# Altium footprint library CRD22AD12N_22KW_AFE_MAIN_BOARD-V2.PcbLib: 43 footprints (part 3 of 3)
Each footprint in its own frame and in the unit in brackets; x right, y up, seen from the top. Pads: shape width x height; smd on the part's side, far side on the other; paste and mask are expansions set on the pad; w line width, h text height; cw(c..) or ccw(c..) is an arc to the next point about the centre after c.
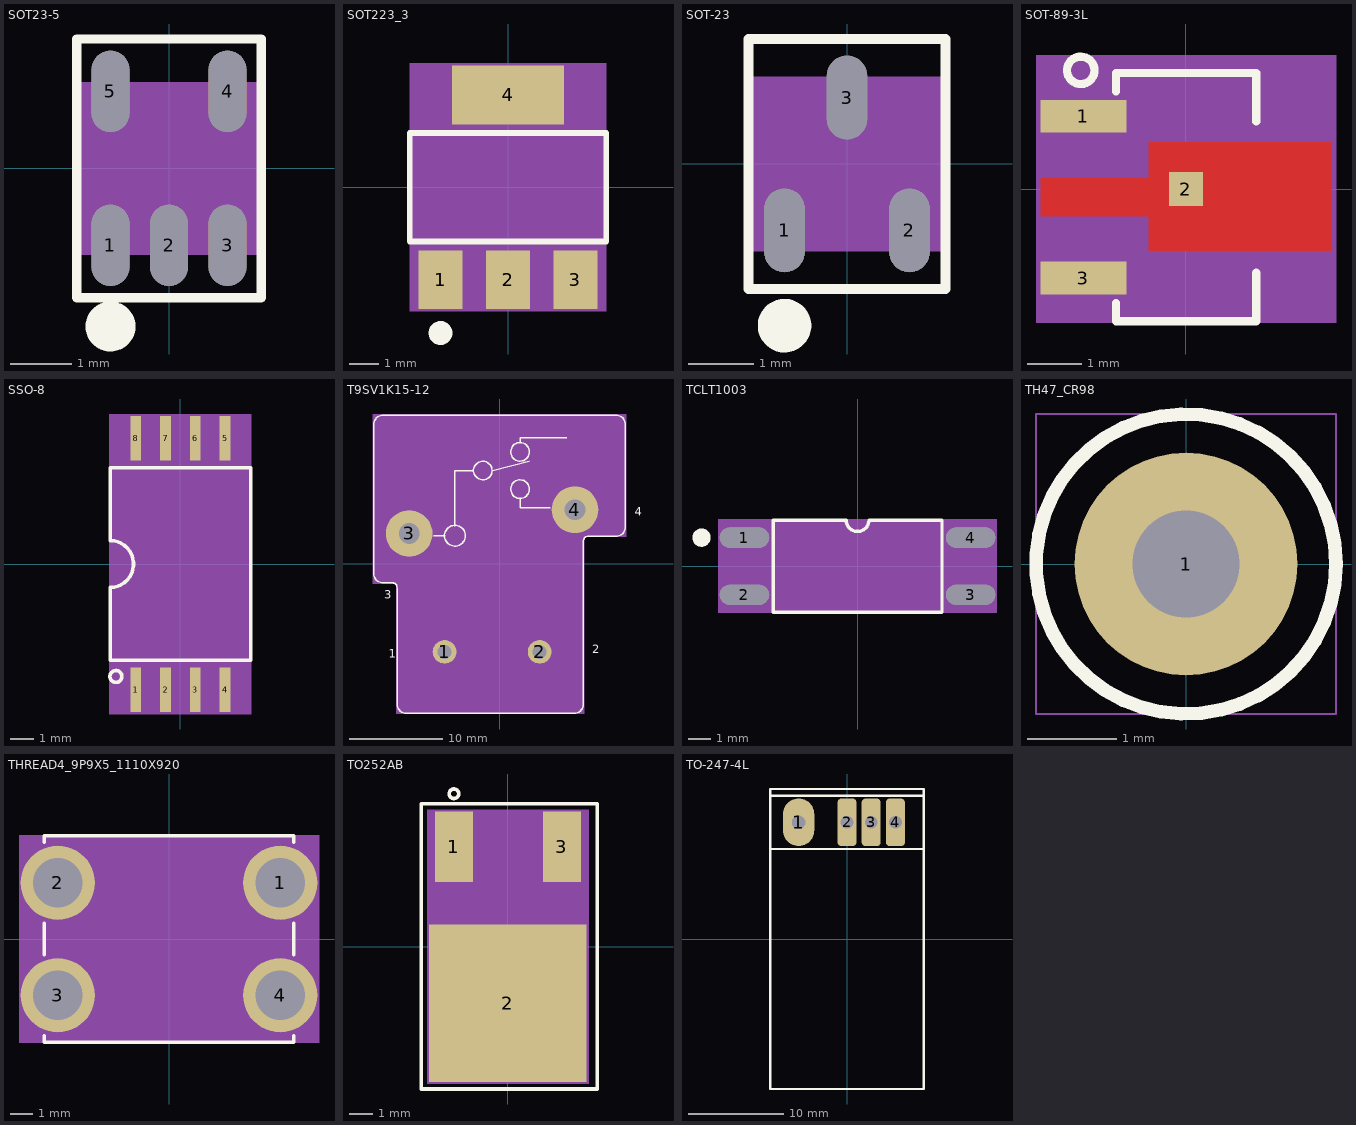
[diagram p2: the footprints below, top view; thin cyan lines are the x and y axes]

## SOT23-5 [mil] "SOT23-5"
pads (5):
  oval 24x52 smd: 1(-37.4,-49.21) 2(0,-49.21) 3(37.4,-49.21) 4(37.4,49.21) 5(-37.4,49.21)
Top Overlay:
  circle w16: c-37.4,-101.11 r8
  lines w6: -59.05,-82.68 59.05,-82.68 59.05,82.68 -59.05,82.68 -59.05,-82.68
Top Courtyard:
  dashed: -57.09,-55.12 -57.09,55.12 57.09,55.12 57.09,-55.12
Top 3D Body:
  region: -57.09,-55.12 -57.09,55.12 57.09,55.12 57.09,-55.12
Top Component Center:
  lines w3: -20,0 20,0 ; 0,-20 0,20
Top Assembly:
  lines w2: -59.05,-33.47 59.05,-33.47 59.05,33.47 -59.05,33.47 -59.05,-33.47
  text "HAMP" at 0,33.6 h31
  text "#TOL" at 0,33.6 h31
  text "MCP6031" at 0,70.8 h31
  text ".Designator" at 0,22 h35
Mechanical 24:
  text "2" at 1.97,-39.41 h25
  text "5" at -39.37,59.41 h25
  text "1" at -37.4,-37.44 h25
  text "3" at 37.4,-39.41 h25
  text "4" at 37.4,59.41 h25
3D body: height 150, standoff 0, extent -57.09,-55.12 57.09,55.12

## SOT223_3 [mil] "SOT223_3"
pads (4):
  rect 59x79 smd: 1(-90.55,-124.02) 2(0,-124.02) 3(90.55,-124.02)
  rect 150x79 smd: 4(0,124.02)
Top Overlay:
  circle w16: c-90.55,-195.52 r8
  lines w7.87: -131.89,-72.84 131.89,-72.84 131.89,72.84 -131.89,72.84 -131.89,-72.84
  text ".Designator" at 245,11.67 h35
Top Courtyard:
  dashed: -131.89,-166.52 131.89,-166.52 131.89,166.52 -131.89,166.52
Top 3D Body:
  region: -131.89,-166.52 131.89,-166.52 131.89,166.52 -131.89,166.52
Top Component Center:
  lines w3: -20,0 20,0 ; 0,-20 0,20
Top Assembly:
  lines w1: -131.89,-72.84 131.89,-72.84 131.89,72.84 -131.89,72.84 -131.89,-72.84
  text "HAMP" at 49.6,-16 h31
  text "#TOL" at 49.6,-16 h31
  text "LT3092EST_SOT223_5" at 223.2,-16 h31
Mechanical 24:
  text "3" at 109.75,-124.02 h48
  text "1" at -71.35,-124.02 h48
  text "4" at 19.2,124.02 h48
  text "2" at 19.2,-124.02 h48
Mechanical 26:
  dashed: -127.95,-166.52 127.95,-166.52 127.95,166.52 -127.95,166.52
3D body: height 150, standoff 0, extent -131.89,-166.52 131.89,166.52

## SOT-23 [mil] "SOT-23"
pads (3):
  oval 24x50 smd: 1(-37.4,-39.76) 2(37.4,-39.76) 3(0,39.76)
Top Overlay:
  circle w16: c-37.4,-96.77 r8.01
  lines w6: -59.06,-74.8 -59.06,74.8 59.06,74.8 59.06,-74.8 -59.06,-74.8
  text ".Designator" at -30,88.33 h35
Top Courtyard:
  lines w1: -59.84,-51.97 -59.84,51.97 59.84,51.97 59.84,-51.97 -59.84,-51.97
Top 3D Body:
  region: -59.84,-51.97 -59.84,51.97 59.84,51.97 59.84,-51.97
Top Component Center:
  lines w3: -20,0 20,0 ; 0,-20 0,20
Top Assembly:
  lines w2: -59.06,-27.56 59.06,-27.56 59.06,27.56 -59.06,27.56 -59.06,-27.56
  text "HAMP" at 0,-65.6 h31
  text "#TOL" at 0,-65.6 h31
  text "2N7002K" at 0,-102.8 h31
Mechanical 24:
  text "2" at 37.4,-43.76 h10
  text "3" at 0,35.76 h10
  text "1" at -37.4,-43.76 h10
3D body: height 150, standoff 0, extent -59.84,-51.97 59.84,51.97

## SOT-89-3L [mil] "SOT-89-3L"
pads (3):
  rect 63x24 smd: 1(-74.78,53.08) 3(-74.78,-65.03)
  rect 25x25 smd mask+0: 2(0,0)
Top Layer:
  region: -106,-20 -106,8 -27,8 -27,34 106,34 106,-45 -27,-45 -27,-20
Top Overlay:
  circle w6: c-76.75,86.54 r10
  lines w6: -51.15,-83.13 -51.15,-96.53 51.21,-96.53 51.21,-61.1 ; -51.15,71.18 -51.15,84.57 51.21,84.57 51.21,49.14
  text ".Designator" at 120,-11.67 h35
Top Courtyard:
  dashed: -109.4,-97.53 109.4,-97.53 109.4,97.53 -109.4,97.53
Top 3D Body:
  region: -109.4,-97.53 109.4,-97.53 109.4,97.53 -109.4,97.53
Top Component Center:
  lines w3: -37.69,-5.98 2.31,-5.98 ; -17.69,-25.98 -17.69,14.02
Top Assembly:
  circle w2: c-76.75,86.54 r10
  lines w2: -51.15,-80.78 -51.15,-96.53 51.21,-96.53 51.21,-61.1 ; -51.15,68.82 -51.15,84.57 51.21,84.57 51.21,49.14
  text "MC78L05F-TP" at -17.69,114.42 h31
  text "#TOL" at -17.69,27.62 h31
  text "HAMP" at -17.69,27.62 h31
Mechanical 24:
  text "1" at -74.78,57.08 h10
  text "3" at -74.78,-61.03 h10
  text "2" at -66.9,-1.98 h10
3D body: height 150, standoff 0, extent -109.4,-97.53 109.4,97.53

## SSO-8 [mil] "SSO-8"
pads (8):
  rect 18x75 smd: 1(-74.84,-211.52) 2(-24.84,-211.52) 3(25.16,-211.52) 4(75.16,-211.52) 5(75.16,211.52) 6(25.16,211.52) 7(-24.84,211.52) 8(-74.84,211.52)
Top Overlay:
  circle w6: c-108.27,-188.98 r10
  lines w6: -117.95,-161.42 -117.95,-39.37 ccw(c-117.95,0) -117.95,39.37 -117.95,161.42 118.27,161.42 118.27,-161.42 -117.95,-161.42
  text ".Designator" at 70,311.67 h35
Top Courtyard:
  dashed: -119.27,-252.02 119.27,-252.02 119.27,252.02 -119.27,252.02
Top 3D Body:
  region: -119.27,-252.02 119.27,-252.02 119.27,252.02 -119.27,252.02
Top Component Center:
  lines w3: -19.84,0 20.16,0 ; 0.16,-20 0.16,20
Top Assembly:
  circle w2: c-108.27,-188.98 r10
  lines w2: -117.95,-161.42 -117.95,-39.37 ccw(c-117.95,0) -117.95,39.37 -117.95,161.42 118.27,161.42 118.27,-161.42 -117.95,-161.42
  text "ACPL-C870-500E" at 173.76,-16 h31
  text "#TOL" at 49.76,-16 h31
  text "HAMP" at 49.76,-16 h31
Mechanical 24:
  text "6" at 29.16,211.52 h10
  text "3" at 29.16,-211.52 h10
  text "4" at 79.16,-211.52 h10
  text "5" at 79.16,211.52 h10
  text "8" at -70.84,211.52 h10
  text "7" at -20.84,211.52 h10
  text "2" at -20.84,-211.52 h10
  text "1" at -70.84,-211.52 h10
3D body: height 150, standoff 0, extent -119.27,-252.02 119.27,252.02

## T9SV1K15-12 [mil] "T9SV1K15-12"
pads (4):
  round 100 hole 59: 1(-232.28,-371.06) 2(169.3,-371.06)
  round 197 hole 87: 3(-381.88,128.94) 4(318.9,229.34)
Top Overlay:
  circle w5.91: c86.61,473.82 r39.37
  circle w5.91: c86.61,316.34 r39.37
  circle w5.91: c-70.86,395.08 r39.37
  circle w5.91: c-188.97,119.49 r44.02
  lines w5.91: -452.75,-79.73 cw(c-452.76,-99.4) -433.08,-99.41 -433.08,-591.54 ccw(c-393.71,-591.53) -393.71,-630.91 314.97,-630.91 ccw(c314.97,-591.53) 354.34,-591.54 354.34,97.44 cw(c374.02,97.45) 374.01,117.12 492.12,117.12 ccw(c492.12,156.5) 531.49,156.5 531.49,176.18 531.49,589.57 ccw(c492.12,589.57) 492.12,628.94 -492.12,628.94 ccw(c-492.12,589.57) -531.49,589.57 -531.49,-40.35 ccw(c-492.12,-40.35) -492.12,-79.72 -452.75,-79.72 ; -277.33,119.49 -228.34,119.49 ; -188.97,158.85 -188.97,395.07 -110.23,395.07 ; -31.49,395.07 125.99,434.44 ; 86.62,276.96 86.62,237.59 214.34,237.59 ; 86.62,513.18 86.62,532.88 283.47,532.88
  text ".Designator" at 432.01,-146.73 h35
  text "3" at -487.99,-146.73 h35
  text "4" at 572.01,203.27 h35
  text "2" at 392.01,-376.73 h35
  text "1" at -467.99,-396.73 h35
Top 3D Body:
  region: -535.43,633.85 535.43,633.85 535.43,114.18 358.27,114.18 358.27,-633.86 -437.01,-633.86 -437.01,-82.67 -535.43,-82.67
Top Component Center:
  lines w3: -51.49,-70.86 -11.49,-70.86 ; -31.49,-90.86 -31.49,-50.86
Top Assembly:
  circle w2: c86.61,473.82 r39.37
  circle w2: c86.61,316.34 r39.37
  circle w2: c-70.86,395.08 r39.37
  circle w2: c-188.97,119.49 r44.02
  lines w2: -452.75,-79.73 cw(c-452.76,-99.4) -433.08,-99.41 -433.08,-591.54 ccw(c-393.71,-591.53) -393.71,-630.91 314.97,-630.91 ccw(c314.97,-591.53) 354.34,-591.54 354.34,97.44 cw(c374.02,97.45) 374.01,117.12 492.12,117.12 ccw(c492.12,156.5) 531.49,156.5 531.49,176.18 531.49,589.57 ccw(c492.12,589.57) 492.12,628.94 -492.12,628.94 ccw(c-492.12,589.57) -531.49,589.57 -531.49,-40.35 ccw(c-492.12,-40.35) -492.12,-79.72 -452.75,-79.72 ; -287.4,119.49 -228.34,119.49 ; -188.97,158.85 -188.97,395.07 -110.23,395.07 ; -31.49,395.07 125.99,434.44 ; 86.62,276.96 86.62,237.59 224.42,237.59 ; 86.62,513.18 86.62,532.88 283.47,532.88
  text "HAMP" at -81.09,-86.86 h31
  text "#TOL" at -81.09,-86.86 h31
  text "832HA-1A-F-C-12VDC" at -254.69,-86.86 h31
Mechanical 24:
  text "1" at -236.28,-371.06 h10
  text "3" at -385.88,128.94 h10
  text "2" at 165.29,-371.06 h10
  text "4" at 314.9,229.33 h10
3D body: height 150, standoff 0, extent -535.43,-633.86 535.43,633.85

## TCLT1003 [mil] "TCLT1003"
pads (4):
  oval 86x35 smd: 1(-197.83,50) 2(-197.83,-50) 3(197.83,-50) 4(197.83,50)
Top Overlay:
  circle w16: c-272.83,50 r8
  lines w6: -147.64,-80.71 -147.64,80.71 -20,80.71 ccw(c0,80.71) 20,80.71 147.64,80.71 147.64,-80.71 -147.64,-80.71
  text ".Designator" at 5,-113.33 h35
Top Courtyard:
  dashed: -243.83,-81.71 -243.83,81.71 243.83,81.71 243.83,-81.71
Top 3D Body:
  region: -243.83,-81.71 -243.83,81.71 243.83,81.71 243.83,-81.71
Top Component Center:
  lines w3: -20,0 20,0 ; 0,-20 0,20
Top Assembly:
  lines w2: -147.64,-80.71 -147.64,80.71 -20,80.71 ccw(c0,80.71) 20,80.71 147.64,80.71 147.64,-80.71 -147.64,-80.71
  text "TCLT1003" at -99.2,-16 h31
  text "#TOL" at -49.6,-16 h31
  text "HAMP" at -49.6,-16 h31
Mechanical 24:
  text "1" at -201.83,50 h10
  text "4" at 193.83,50 h10
  text "2" at -201.83,-50 h10
  text "3" at 193.83,-50 h10
3D body: height 150, standoff 0, extent -243.83,-81.71 243.83,81.71

## TH47_CR98 [mil] "TH47_CR98"
pads (1):
  round 98 hole 47: 1(0,0)
Top Overlay:
  circle w6: c0,0 r66.04
Top Courtyard:
  lines w1: -66.04,-66.04 66.04,-66.04 66.04,66.04 -66.04,66.04 -66.04,-66.04
Top 3D Body:
  lines w1: -66.04,-66.04 66.04,-66.04 66.04,66.04 -66.04,66.04 -66.04,-66.04
Top Component Center:
  lines w3: -20,0 20,0 ; 0,-20 0,20
Top Assembly:
  circle w2: c0,0 r66.05
  text ".Designator" at -42,-20 h35
  text "T1T2" at -49.6,-16 h31
  text "#TOL" at -49.6,-16 h31
  text "HAMP" at -49.6,-16 h31
Mechanical 24:
  text "1" at -4,0 h10

## THREAD4_9P9X5_1110X920 [mil] "THREAD4_9P9X5_1110X920"
pads (4):
  round 130 / inner round 99 / far side round 130 hole 87: 1(194.88,98.42) 2(-194.88,98.42) 3(-194.88,-98.42) 4(194.88,-98.42)
Top Overlay:
  lines w6: -218.5,-169.53 -218.5,-181.1 218.5,-181.1 218.5,-169.53 ; -218.5,-27.32 -218.5,27.32 ; -218.5,169.53 -218.5,181.1 218.5,181.1 218.5,169.53 ; 218.5,-27.32 218.5,27.32
  text ".Designator" at 40,260 h35
Top Courtyard:
  dashed: -262.88,-182.09 262.88,-182.09 262.88,182.09 -262.88,182.09
Top 3D Body:
  region: -262.88,-182.09 262.88,-182.09 262.88,182.09 -262.88,182.09
Top Component Center:
  lines w3: -20,0 20,0 ; 0,-20 0,20
Top Assembly:
  lines w2: -218.5,-181.1 -218.5,181.1 218.5,181.1 218.5,-181.1 -218.5,-181.1
  text "Connecter" at 0,-127.6 h31
  text "#TOL" at 0,-65.6 h31
  text "HAMP" at 0,-65.6 h31
Mechanical 24:
  text "4" at 194.88,-108.42 h25
  text "1" at 194.88,88.42 h25
  text "3" at -194.88,-108.42 h25
  text "2" at -194.88,88.42 h25
3D body: height 150, standoff 0, extent -262.88,-182.09 262.88,182.09

## TO252AB [mil] "TO252AB"
pads (3):
  rect 63x118 smd: 1(-90.55,167.41) 3(90.55,167.41)
  rect 264x264 smd: 2(0,-94.41)
Top Overlay:
  circle w6: c-90.55,256.44 r8
  lines w6: -145.67,-238.5 -145.67,239.85 149.61,239.85 149.61,-238.5 -59.06,-238.5 -145.67,-238.5
  text ".Designator" at 20.39,301.86 h35
Top Paste:
  dashed: 126.05,31.64 126.05,-9.26 85.15,-9.26 85.15,31.64
  dashed: 126.05,-21.15 126.05,-62.06 85.15,-62.06 85.15,-21.15
  dashed: 126.05,-73.96 126.05,-114.86 85.15,-114.86 85.15,-73.96
  dashed: 126.05,-126.76 126.05,-167.65 85.15,-167.65 85.15,-126.76
  dashed: 126.05,-179.56 126.05,-220.46 85.15,-220.46 85.15,-179.56
  dashed: 73.25,31.64 73.25,-9.26 32.35,-9.26 32.35,31.64
  dashed: 73.25,-21.15 73.25,-62.06 32.35,-62.06 32.35,-21.15
  dashed: 73.25,-73.96 73.25,-114.86 32.35,-114.86 32.35,-73.96
  dashed: 73.25,-126.76 73.25,-167.65 32.35,-167.65 32.35,-126.76
  dashed: 73.25,-179.56 73.25,-220.46 32.35,-220.46 32.35,-179.56
  dashed: 20.45,31.64 20.45,-9.26 -20.45,-9.26 -20.45,31.64
  dashed: 20.45,-21.15 20.45,-62.06 -20.45,-62.06 -20.45,-21.15
  dashed: 20.45,-73.96 20.45,-114.86 -20.45,-114.86 -20.45,-73.96
  dashed: 20.45,-126.76 20.45,-167.65 -20.45,-167.65 -20.45,-126.76
  dashed: 20.45,-179.56 20.45,-220.46 -20.45,-220.46 -20.45,-179.56
  dashed: -32.35,31.64 -32.35,-9.26 -73.25,-9.26 -73.25,31.64
  dashed: -32.35,-21.15 -32.35,-62.06 -73.25,-62.06 -73.25,-21.15
  dashed: -32.35,-73.96 -32.35,-114.86 -73.25,-114.86 -73.25,-73.96
  dashed: -32.35,-126.76 -32.35,-167.65 -73.25,-167.65 -73.25,-126.76
  dashed: -32.35,-179.56 -32.35,-220.46 -73.25,-220.46 -73.25,-179.56
  dashed: -85.15,31.64 -85.15,-9.26 -126.05,-9.26 -126.05,31.64
  dashed: -85.15,-21.15 -85.15,-62.06 -126.05,-62.06 -126.05,-21.15
  dashed: -85.15,-73.96 -85.15,-114.86 -126.05,-114.86 -126.05,-73.96
  dashed: -85.15,-126.76 -85.15,-167.65 -126.05,-167.65 -126.05,-126.76
  dashed: -85.15,-179.56 -85.15,-220.46 -126.05,-220.46 -126.05,-179.56
Top Courtyard:
  dashed: 135,229.41 135,-229.41 -135,-229.41 -135,229.41
Top 3D Body:
  region: 135,229.41 135,-229.41 -135,-229.41 -135,229.41
Top Component Center:
  lines w3: -20,-114.48 20,-114.48 ; 0,-134.49 0,-94.48
Top Assembly:
  lines w2: -129.92,-214.88 -129.92,25.27 129.92,25.27 129.92,-214.88 -129.92,-214.88
  text "LF50ABDT-TR" at -136.4,-98.48 h31
  text "#TOL" at -49.6,-98.48 h31
  text "HAMP" at -49.6,-98.48 h31
Mechanical 24:
  text "2" at -4,-94.41 h10
  text "3" at 86.55,167.41 h10
  text "1" at -94.55,167.41 h10
3D body: height 150, standoff 0, extent -135,-229.41 135,229.41

## TO-247-4L [mm] "TO-247-4L"
pads (4):
  oval 3.302x5.004 hole 1.397: 1(-5.08,12.25)
  rrect40% 2x5 hole 1.346: 2(0,12.25) 3(2.54,12.25) 4(5.08,12.25)
Top Overlay:
  lines w0.25: -8.065,14.77 -8.065,15.75 8.065,15.75 8.065,14.71
  lines w0.254: -8.065,-15.75 -8.065,15.75 8.065,15.75 8.065,-15.75 -8.065,-15.75 ; -8.065,9.45 -8.065,15.05 8.065,15.05 8.065,9.45 -8.065,9.45
Top Courtyard:
  lines w0.025: -8.065,-15.75 -8.065,15.75 8.065,15.75 8.065,-15.75 -8.065,-15.75
Top 3D Body:
  lines w0.025: -8.065,-15.75 -8.065,15.75 8.065,15.75 8.065,-15.75 -8.065,-15.75
Top Component Center:
  lines w0.076: -0.508,12.25 0.508,12.25 ; 0,11.742 0,12.758
Top Assembly:
  lines w0.025: -8.065,14.77 -8.065,15.75 ; 8.065,14.71 8.065,15.75 ; -8.065,15.75 -8.065,-15.75 8.065,-15.75 8.065,15.75 ; -8.065,15.75 8.065,15.75 ; -8.065,15.75 8.065,15.75 ; -8.065,9.45 8.065,9.45 8.065,15.05 -8.065,15.05 -8.065,9.45
  text ".Designator" at 0,11.031 h0.89
  text "C3M0021120K" at 0,8.379 h0.79
  text "#TOL" at 0,10.584 h0.79
  text "HAMP" at 0,10.584 h0.79
Mechanical 24:
  text "1" at -5.08,11.894 h0.89
  text "4" at 5.08,11.894 h0.89
  text "3" at 2.54,11.894 h0.89
  text "2" at 0,11.894 h0.89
